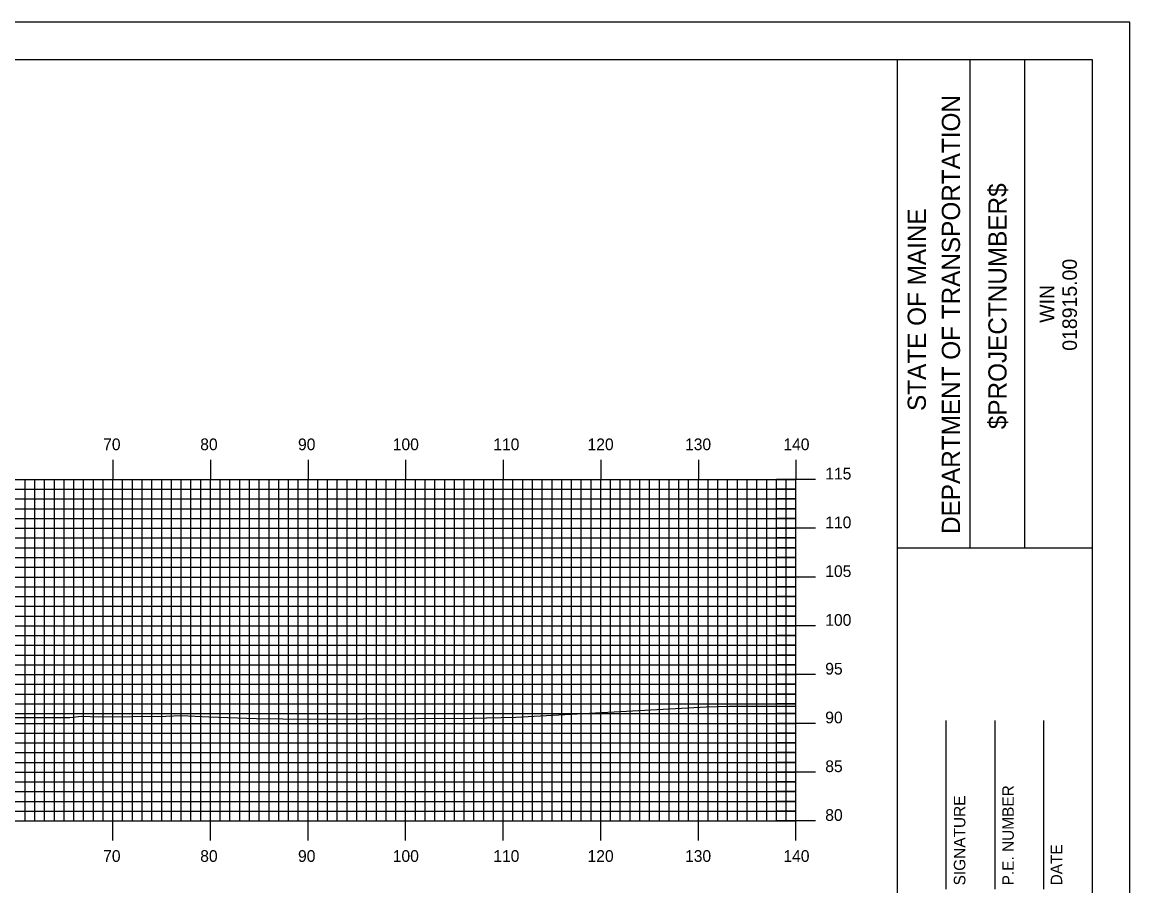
# Model space of a CAD drawing. Extents: x 1760217 to 1760560, y 442591 to 442811.
# Drawn here: x 1760443.4 to 1760556.9, y 442722 to 442810.5 of the extents above; entities that cross this region are included whole.
import ezdxf

# ---------------------------------------------------------------- set-up
doc = ezdxf.new("R2010")
doc.units = 0
for name, color, linetype in [('BORDER', 7, 'Continuous'), ('H_V ANNOTATION', 7, 'Continuous'), ('MAJOR', 7, 'Continuous'), ('MINOR', 7, 'Continuous'), ('PLOT BOUNDARY', 7, 'Continuous'), ('S_Roadway_Centerline', 7, 'Continuous')]:
    doc.layers.add(name, color=color, linetype=linetype)

msp = doc.modelspace()

# ---------------------------------------------------------------- linework, layer by layer
at = {"layer": 'BORDER'}
for p, q in [((1760533.1, 442596.67), (1760533.1, 442806.67)), ((1760540.56, 442756.66), (1760540.56, 442806.66)), ((1760546.15, 442756.66), (1760546.15, 442806.66)), ((1760533.1, 442756.65), (1760553.1, 442756.65)), ((1760538.1, 442721.67), (1760538.1, 442738.97)), ((1760543.1, 442721.67), (1760543.1, 442738.97)), ((1760548.1, 442721.67), (1760548.1, 442738.97))]:
    msp.add_line(p, q, dxfattribs=at)
msp.add_lwpolyline([(1760233.1, 442596.67), (1760553.1, 442596.67), (1760553.1, 442806.67), (1760233.1, 442806.67)], close=True, dxfattribs=at)
at = {"layer": 'MAJOR'}
for p, q in [((1760452.7, 442765.67), (1760452.7, 442763.67)), ((1760462.7, 442765.67), (1760462.7, 442763.67)), ((1760472.7, 442765.67), (1760472.7, 442763.67)), ((1760482.7, 442765.67), (1760482.7, 442763.67)), ((1760492.7, 442765.67), (1760492.7, 442763.67)), ((1760502.7, 442765.67), (1760502.7, 442763.67)), ((1760512.7, 442765.67), (1760512.7, 442763.67)), ((1760522.7, 442765.67), (1760522.7, 442763.67)), ((1760242.7, 442763.67), (1760522.7, 442763.67)), ((1760242.7, 442763.67), (1760522.7, 442763.67)), ((1760452.7, 442728.67), (1760452.7, 442763.67)), ((1760462.7, 442728.67), (1760462.7, 442763.67)), ((1760472.7, 442728.67), (1760472.7, 442763.67)), ((1760482.7, 442728.67), (1760482.7, 442763.67)), ((1760492.7, 442728.67), (1760492.7, 442763.67)), ((1760502.7, 442728.67), (1760502.7, 442763.67)), ((1760512.7, 442728.67), (1760512.7, 442763.67)), ((1760524.7, 442763.67), (1760520.7, 442763.67)), ((1760522.7, 442728.67), (1760522.7, 442763.67)), ((1760522.7, 442728.67), (1760522.7, 442763.67)), ((1760242.7, 442758.67), (1760522.7, 442758.67)), ((1760524.7, 442758.67), (1760520.7, 442758.67)), ((1760242.7, 442753.67), (1760522.7, 442753.67)), ((1760524.7, 442753.67), (1760520.7, 442753.67)), ((1760242.7, 442748.67), (1760522.7, 442748.67)), ((1760524.7, 442748.67), (1760520.7, 442748.67)), ((1760242.7, 442743.67), (1760522.7, 442743.67)), ((1760524.7, 442743.67), (1760520.7, 442743.67)), ((1760242.7, 442738.67), (1760522.7, 442738.67)), ((1760524.7, 442738.67), (1760520.7, 442738.67)), ((1760242.7, 442733.67), (1760522.7, 442733.67)), ((1760524.7, 442733.67), (1760520.7, 442733.67)), ((1760242.7, 442728.67), (1760522.7, 442728.67)), ((1760242.7, 442728.67), (1760522.7, 442728.67)), ((1760452.7, 442726.66), (1760452.7, 442728.67)), ((1760462.7, 442726.66), (1760462.7, 442728.67)), ((1760472.7, 442726.66), (1760472.7, 442728.67)), ((1760482.7, 442726.66), (1760482.7, 442728.67)), ((1760492.7, 442726.66), (1760492.7, 442728.67)), ((1760502.7, 442726.66), (1760502.7, 442728.67)), ((1760512.7, 442726.66), (1760512.7, 442728.67)), ((1760524.7, 442728.67), (1760520.7, 442728.67)), ((1760522.7, 442726.66), (1760522.7, 442728.67))]:
    msp.add_line(p, q, dxfattribs=at)
at = {"layer": 'MINOR'}
for p, q in [((1760443.7, 442728.67), (1760443.7, 442763.67)), ((1760444.7, 442728.67), (1760444.7, 442763.67)), ((1760445.7, 442728.67), (1760445.7, 442763.67)), ((1760446.7, 442728.67), (1760446.7, 442763.67)), ((1760447.7, 442728.67), (1760447.7, 442763.67)), ((1760448.7, 442728.67), (1760448.7, 442763.67)), ((1760449.7, 442728.67), (1760449.7, 442763.67)), ((1760450.7, 442728.67), (1760450.7, 442763.67)), ((1760451.7, 442728.67), (1760451.7, 442763.67)), ((1760453.7, 442728.67), (1760453.7, 442763.67)), ((1760454.7, 442728.67), (1760454.7, 442763.67)), ((1760455.7, 442728.67), (1760455.7, 442763.67)), ((1760456.7, 442728.67), (1760456.7, 442763.67)), ((1760457.7, 442728.67), (1760457.7, 442763.67)), ((1760458.7, 442728.67), (1760458.7, 442763.67)), ((1760459.7, 442728.67), (1760459.7, 442763.67)), ((1760460.7, 442728.67), (1760460.7, 442763.67)), ((1760461.7, 442728.67), (1760461.7, 442763.67)), ((1760463.7, 442728.67), (1760463.7, 442763.67)), ((1760464.7, 442728.67), (1760464.7, 442763.67)), ((1760465.7, 442728.67), (1760465.7, 442763.67)), ((1760466.7, 442728.67), (1760466.7, 442763.67)), ((1760467.7, 442728.67), (1760467.7, 442763.67)), ((1760468.7, 442728.67), (1760468.7, 442763.67)), ((1760469.7, 442728.67), (1760469.7, 442763.67)), ((1760470.7, 442728.67), (1760470.7, 442763.67)), ((1760471.7, 442728.67), (1760471.7, 442763.67)), ((1760473.7, 442728.67), (1760473.7, 442763.67)), ((1760474.7, 442728.67), (1760474.7, 442763.67)), ((1760475.7, 442728.67), (1760475.7, 442763.67)), ((1760476.7, 442728.67), (1760476.7, 442763.67)), ((1760477.7, 442728.67), (1760477.7, 442763.67)), ((1760478.7, 442728.67), (1760478.7, 442763.67)), ((1760479.7, 442728.67), (1760479.7, 442763.67)), ((1760480.7, 442728.67), (1760480.7, 442763.67)), ((1760481.7, 442728.67), (1760481.7, 442763.67)), ((1760483.7, 442728.67), (1760483.7, 442763.67)), ((1760484.7, 442728.67), (1760484.7, 442763.67)), ((1760485.7, 442728.67), (1760485.7, 442763.67)), ((1760486.7, 442728.67), (1760486.7, 442763.67)), ((1760487.7, 442728.67), (1760487.7, 442763.67)), ((1760488.7, 442728.67), (1760488.7, 442763.67)), ((1760489.7, 442728.67), (1760489.7, 442763.67)), ((1760490.7, 442728.67), (1760490.7, 442763.67)), ((1760491.7, 442728.67), (1760491.7, 442763.67)), ((1760493.7, 442728.67), (1760493.7, 442763.67)), ((1760494.7, 442728.67), (1760494.7, 442763.67)), ((1760495.7, 442728.67), (1760495.7, 442763.67)), ((1760496.7, 442728.67), (1760496.7, 442763.67)), ((1760497.7, 442728.67), (1760497.7, 442763.67)), ((1760498.7, 442728.67), (1760498.7, 442763.67)), ((1760499.7, 442728.67), (1760499.7, 442763.67)), ((1760500.7, 442728.67), (1760500.7, 442763.67)), ((1760501.7, 442728.67), (1760501.7, 442763.67)), ((1760503.7, 442728.67), (1760503.7, 442763.67)), ((1760504.7, 442728.67), (1760504.7, 442763.67)), ((1760505.7, 442728.67), (1760505.7, 442763.67)), ((1760506.7, 442728.67), (1760506.7, 442763.67)), ((1760507.7, 442728.67), (1760507.7, 442763.67)), ((1760508.7, 442728.67), (1760508.7, 442763.67)), ((1760509.7, 442728.67), (1760509.7, 442763.67)), ((1760510.7, 442728.67), (1760510.7, 442763.67)), ((1760511.7, 442728.67), (1760511.7, 442763.67)), ((1760513.7, 442728.67), (1760513.7, 442763.67)), ((1760514.7, 442728.67), (1760514.7, 442763.67)), ((1760515.7, 442728.67), (1760515.7, 442763.67)), ((1760516.7, 442728.67), (1760516.7, 442763.67)), ((1760517.7, 442728.67), (1760517.7, 442763.67)), ((1760518.7, 442728.67), (1760518.7, 442763.67)), ((1760519.7, 442728.67), (1760519.7, 442763.67)), ((1760520.7, 442728.67), (1760520.7, 442763.67)), ((1760521.7, 442728.67), (1760521.7, 442763.67)), ((1760242.7, 442762.67), (1760522.7, 442762.67)), ((1760522.7, 442762.67), (1760520.7, 442762.67)), ((1760242.7, 442761.67), (1760522.7, 442761.67)), ((1760522.7, 442761.67), (1760520.7, 442761.67)), ((1760242.7, 442760.67), (1760522.7, 442760.67)), ((1760522.7, 442760.67), (1760520.7, 442760.67)), ((1760242.7, 442759.67), (1760522.7, 442759.67)), ((1760522.7, 442759.67), (1760520.7, 442759.67)), ((1760242.7, 442757.67), (1760522.7, 442757.67)), ((1760522.7, 442757.67), (1760520.7, 442757.67)), ((1760242.7, 442756.67), (1760522.7, 442756.67)), ((1760522.7, 442756.67), (1760520.7, 442756.67)), ((1760242.7, 442755.67), (1760522.7, 442755.67)), ((1760522.7, 442755.67), (1760520.7, 442755.67)), ((1760242.7, 442754.67), (1760522.7, 442754.67)), ((1760522.7, 442754.67), (1760520.7, 442754.67)), ((1760242.7, 442752.67), (1760522.7, 442752.67)), ((1760522.7, 442752.67), (1760520.7, 442752.67)), ((1760242.7, 442751.67), (1760522.7, 442751.67)), ((1760522.7, 442751.67), (1760520.7, 442751.67)), ((1760242.7, 442750.67), (1760522.7, 442750.67)), ((1760242.7, 442749.67), (1760522.7, 442749.67)), ((1760522.7, 442750.67), (1760520.7, 442750.67)), ((1760522.7, 442749.67), (1760520.7, 442749.67)), ((1760242.7, 442747.67), (1760522.7, 442747.67)), ((1760522.7, 442747.67), (1760520.7, 442747.67)), ((1760242.7, 442746.67), (1760522.7, 442746.67)), ((1760522.7, 442746.67), (1760520.7, 442746.67)), ((1760242.7, 442745.67), (1760522.7, 442745.67)), ((1760522.7, 442745.67), (1760520.7, 442745.67)), ((1760242.7, 442744.67), (1760522.7, 442744.67)), ((1760522.7, 442744.67), (1760520.7, 442744.67)), ((1760242.7, 442742.67), (1760522.7, 442742.67)), ((1760242.7, 442741.67), (1760522.7, 442741.67)), ((1760522.7, 442742.67), (1760520.7, 442742.67)), ((1760522.7, 442741.67), (1760520.7, 442741.67)), ((1760242.7, 442740.67), (1760522.7, 442740.67)), ((1760522.7, 442740.67), (1760520.7, 442740.67)), ((1760242.7, 442739.67), (1760522.7, 442739.67)), ((1760522.7, 442739.67), (1760520.7, 442739.67)), ((1760242.7, 442737.67), (1760522.7, 442737.67)), ((1760522.7, 442737.67), (1760520.7, 442737.67)), ((1760242.7, 442736.67), (1760522.7, 442736.67)), ((1760522.7, 442736.67), (1760520.7, 442736.67)), ((1760242.7, 442735.67), (1760522.7, 442735.67)), ((1760522.7, 442735.67), (1760520.7, 442735.67)), ((1760242.7, 442734.67), (1760522.7, 442734.67)), ((1760522.7, 442734.67), (1760520.7, 442734.67)), ((1760242.7, 442732.67), (1760522.7, 442732.67)), ((1760522.7, 442732.67), (1760520.7, 442732.67)), ((1760242.7, 442731.67), (1760522.7, 442731.67)), ((1760522.7, 442731.67), (1760520.7, 442731.67)), ((1760242.7, 442730.67), (1760522.7, 442730.67)), ((1760522.7, 442730.67), (1760520.7, 442730.67)), ((1760242.7, 442729.67), (1760522.7, 442729.67)), ((1760522.7, 442729.67), (1760520.7, 442729.67))]:
    msp.add_line(p, q, dxfattribs=at)
at = {"layer": 'PLOT BOUNDARY'}
msp.add_lwpolyline([(1760216.91, 442590.55), (1760556.91, 442590.55), (1760556.91, 442810.55), (1760216.91, 442810.55)], close=True, dxfattribs=at)
at = {"layer": 'S_Roadway_Centerline'}
msp.add_lwpolyline([(1760439.7, 442739.27), (1760448.3, 442739.28), (1760449.48, 442739.42), (1760451.25, 442739.33), (1760458.11, 442739.42), (1760459.73, 442739.46), (1760462.53, 442739.34), (1760467.43, 442739.17), (1760472.8, 442739.1), (1760489.47, 442739.2), (1760493.99, 442739.29), (1760513.48, 442740.37), (1760515.84, 442740.42), (1760522.7, 442740.44)], dxfattribs=at)

# ---------------------------------------------------------------- texts
at = {"layer": 'BORDER'}
for s, height, p in [('DEPARTMENT OF TRANSPORTATION', 1.8635, (1760539.51, 442758.08)), ('$PROJECTNUMBER$', 1.8635, (1760544.28, 442768.82)), ('STATE OF MAINE', 1.8635, (1760536.01, 442770.69)), ('018915.00', 1.491, (1760551.49, 442776.86)), ('WIN', 1.491, (1760549.17, 442779.73)), ('P.E. NUMBER', 1.1811, (1760545.02, 442722.06)), ('SIGNATURE', 1.181, (1760540.06, 442722.06)), ('DATE', 1.181, (1760549.98, 442722.06))]:
    msp.add_text(s, height=height, rotation=90, dxfattribs=at).set_placement(p)
at = {"layer": 'H_V ANNOTATION'}
for s, p in [('70', (1760451.7, 442766.67)), ('80', (1760461.65, 442766.67)), ('90', (1760471.67, 442766.67)), ('100', (1760481.38, 442766.67)), ('110', (1760491.68, 442766.67)), ('120', (1760501.34, 442766.67)), ('130', (1760511.33, 442766.67)), ('140', (1760521.41, 442766.67)), ('115', (1760525.7, 442763.67)), ('110', (1760525.7, 442758.67)), ('105', (1760525.7, 442753.67)), ('100', (1760525.7, 442748.67)), ('95', (1760525.7, 442743.67)), ('90', (1760525.7, 442738.67)), ('85', (1760525.7, 442733.67)), ('80', (1760525.7, 442728.67)), ('70', (1760451.7, 442724.47)), ('80', (1760461.65, 442724.47)), ('90', (1760471.67, 442724.47)), ('100', (1760481.38, 442724.47)), ('110', (1760491.68, 442724.47)), ('120', (1760501.34, 442724.47)), ('130', (1760511.33, 442724.47)), ('140', (1760521.41, 442724.47))]:
    msp.add_text(s, height=1.2, dxfattribs=at).set_placement(p)

doc.saveas('drawing.dxf')
